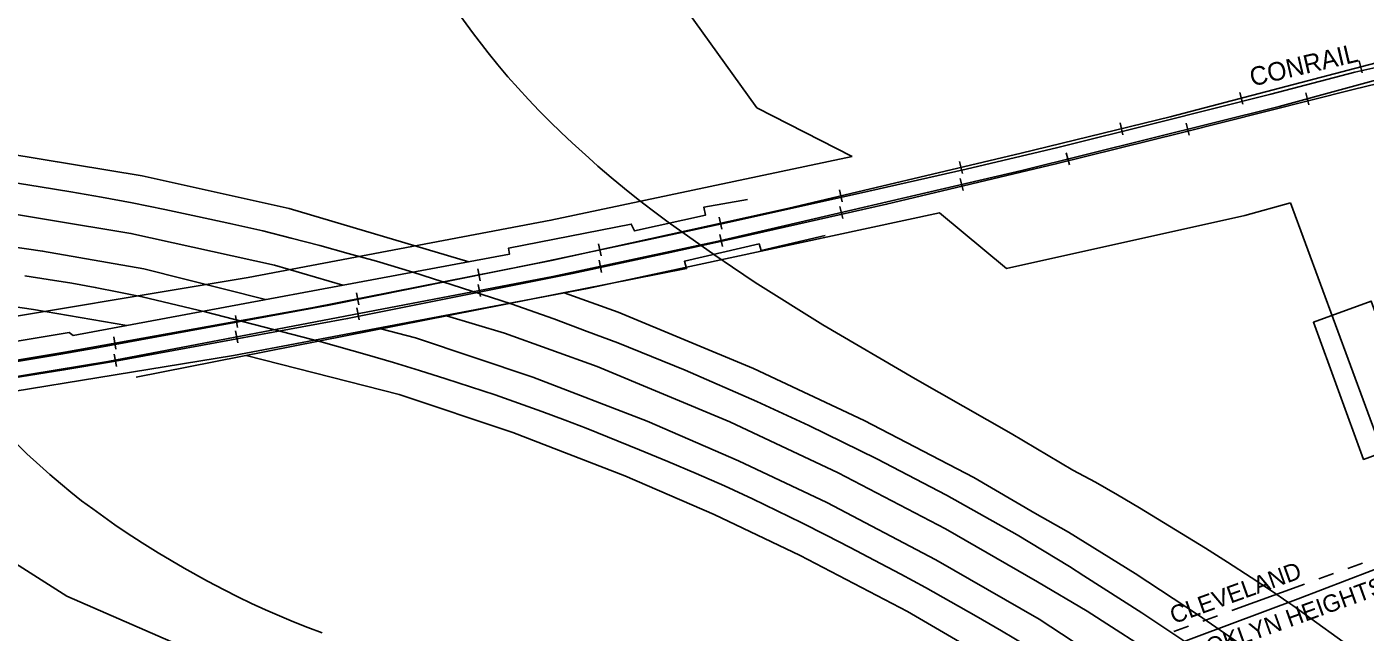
# Model space of a CAD drawing. Extents: x -25029 to 2274964, y -81170 to 687028.
# Drawn here: x -16160 to -15076, y -64135 to -63645 of the extents above; entities that cross this region are included whole.
import ezdxf

# ---------------------------------------------------------------- set-up
doc = ezdxf.new("R2010")
doc.units = 0
for name, color, linetype in [('81911BEA - RW_X_Fee_RW', 7, 'Continuous'), ('BLDG', 7, 'Continuous'), ('BRIDGE', 7, 'Continuous'), ('DIVISIONS', 7, 'Continuous'), ('DV_X_Corp_Line', 7, 'Continuous'), ('GE_X_CL_100', 7, 'Continuous'), ('GE_X_CL_2000', 7, 'Continuous'), ('INTERSTATE', 7, 'Continuous'), ('PV_X_EOP', 7, 'Continuous'), ('RD_X_RR_1', 7, 'Continuous'), ('ROAD-NAME', 7, 'Continuous'), ('RR', 7, 'Continuous'), ('WALL', 7, 'Continuous')]:
    doc.layers.add(name, color=color, linetype=linetype)

msp = doc.modelspace()

# ---------------------------------------------------------------- linework, layer by layer
at = {"layer": '81911BEA - RW_X_Fee_RW'}
for p, q in [((-15569, -63710.4), (-15491.7, -63749.7)), ((-15043.9, -64039.7), (-15136.9, -63787.3)), ((-15421.1, -63795.3), (-15366.8, -63840.5)), ((-16127.7, -64105.8), (-16043.6, -64142.6))]:
    msp.add_line(p, q, dxfattribs=at)
for points in [[(-15569, -63710.4), (-15570.4, -63708.5), (-15618.7, -63641.2), (-15786.7, -63407.4)], [(-16227.1, -63888.9), (-15981, -63847.8), (-15735.8, -63801.4), (-15491.7, -63749.7)], [(-15366.8, -63840.5), (-15173.7, -63797.6), (-15136.9, -63787.3)], [(-16280.7, -63957.8), (-15992.8, -63910.9), (-15706.2, -63856.7), (-15421.1, -63795.3)], [(-16267.9, -64016.5), (-16169.4, -64079.3), (-16127.7, -64105.8)]]:
    msp.add_lwpolyline(points, dxfattribs=at)
at = {"layer": 'BLDG'}
msp.add_lwpolyline([(-15030.9, -63978), (-15071.5, -63866.9), (-15118.3, -63884), (-15077.7, -63995.1)], close=True, dxfattribs=at)
at = {"layer": 'BRIDGE'}
for points in [[(-16122.6, -63894.8), (-15769.3, -63828.8), (-15770.2, -63824.1), (-15670.7, -63804.5), (-15668.2, -63810), (-15610.7, -63797.3), (-15612, -63790.8), (-15576.5, -63784.5)], [(-15513.8, -63813.8), (-15565.6, -63826), (-15567.2, -63820.6), (-15627.7, -63834.6), (-15625.9, -63840.5), (-16071.7, -63928.6)]]:
    msp.add_lwpolyline(points, dxfattribs=at)
at = {"layer": 'DIVISIONS'}
for p, q in [((-15090.3, -64083.3), (-15078.5, -64079)), ((-15113.8, -64091.8), (-15102, -64087.6)), ((-15184.3, -64117.4), (-15125.5, -64096.1)), ((-15207.8, -64126), (-15196, -64121.7)), ((-15231.3, -64134.5), (-15219.5, -64130.2))]:
    msp.add_line(p, q, dxfattribs=at)
at = {"layer": 'DV_X_Corp_Line'}
for p, q in [((-15130.6, -64108.1), (-14835.3, -63994.1)), ((-15130.6, -64108.1), (-14835.3, -63994.1)), ((-14835.3, -63994.1), (-15130.6, -64108.1)), ((-14835.3, -63994.1), (-15130.6, -64108.1)), ((-16057.5, -64452.9), (-15130.6, -64108.1)), ((-16057.5, -64452.9), (-15130.6, -64108.1)), ((-15130.6, -64108.1), (-16057.5, -64452.9)), ((-15130.6, -64108.1), (-16057.5, -64452.9))]:
    msp.add_line(p, q, dxfattribs=at)
at = {"layer": 'GE_X_CL_2000'}
for points in [[(-15139, -64110.6), (-15152.3, -64101.5), (-15168.8, -64090.6), (-15187.8, -64078.3), (-15205.7, -64067.1), (-15259.1, -64034.3), (-15276.9, -64023.8), (-15294.8, -64013.5), (-15313, -64003.7), (-15363.1, -63974.2), (-15440.7, -63929.8), (-15515.7, -63886.2), (-15570.4, -63851.9), (-15588.7, -63839.5), (-15603.1, -63829.7), (-15640.7, -63803), (-15653.9, -63793.3), (-15665.1, -63784.7), (-15676.1, -63775.8), (-15687, -63766.8), (-15697.7, -63757.6), (-15705.2, -63750.9), (-15718.6, -63738.7), (-15727.6, -63730.2), (-15736.6, -63721.5), (-15745.4, -63712.7), (-15754, -63703.7), (-15762.4, -63694.5), (-15770.7, -63685.1), (-15778.7, -63675.6), (-15786.7, -63665.9), (-15799.4, -63649.2), (-15811.8, -63632.4)], [(-15223.2, -64141.9), (-15257.3, -64119.3), (-15304.1, -64089.4), (-15315.9, -64081.8), (-15358.3, -64056.2), (-15415.5, -64024.1), (-15471.9, -63994.6), (-15527, -63967.5), (-15568.9, -63948.2), (-15627, -63922.8), (-15681.7, -63900.8), (-15706.4, -63891.4), (-15733.5, -63881.1), (-15768, -63869), (-15847.7, -63843.3), (-15877.1, -63834.6), (-15900, -63828.2), (-15922.9, -63821.9), (-15946, -63815.9), (-15969.2, -63810), (-15995.7, -63804), (-16022, -63798.3), (-16048.4, -63792.7), (-16074.8, -63787.4), (-16099.7, -63782.8), (-16124.6, -63778.4), (-16149.4, -63774.2), (-16174.5, -63770.2)], [(-16161.9, -63846.5), (-16142.8, -63849.3), (-16123.8, -63852.4), (-16104.8, -63855.8), (-16085.8, -63859.5), (-16066.7, -63863.4), (-16015.9, -63875.6), (-15921.8, -63899.9), (-15884.6, -63910.3), (-15863.3, -63916.5), (-15842.1, -63923), (-15820.9, -63929.7), (-15781, -63942.9), (-15762.1, -63949.5), (-15743.1, -63956.3), (-15724.3, -63963.3), (-15707.1, -63969.9), (-15664, -63987.2), (-15641, -63996.7), (-15618.1, -64006.6), (-15595.3, -64016.6), (-15572.5, -64027), (-15552.5, -64036.7), (-15532.7, -64046.4), (-15513, -64056.4), (-15493.4, -64066.5), (-15474, -64076.8), (-15452.4, -64088.1), (-15432.5, -64098.9), (-15411.8, -64110.3), (-15391.3, -64122), (-15370.9, -64133.9), (-15350.9, -64145.9)], [(-16185.9, -63965.4), (-16160.2, -63990.5), (-16149.8, -63999.9), (-16141.5, -64007.3), (-16133, -64014.5), (-16124.5, -64021.5), (-16115.8, -64028.5), (-16106.8, -64035.2), (-16097.9, -64041.7), (-16088.9, -64048.2), (-16079.7, -64054.4), (-16066.7, -64062.7), (-16053.8, -64070.8), (-16032.7, -64083.1), (-16014, -64093.6), (-16000.5, -64100.8), (-15989.4, -64106.3), (-15978.3, -64111.7), (-15967, -64116.9), (-15955.7, -64121.9), (-15944.3, -64126.6), (-15932.7, -64131.2), (-15921.1, -64135.5)], [(-14895.8, -64307.4), (-14896, -64307.2), (-14906.3, -64298.1), (-14920.8, -64286), (-14926.1, -64281.6), (-14978.1, -64235), (-15032, -64190.2), (-15082.5, -64151.1), (-15115.4, -64127.4), (-15134.9, -64113.3), (-15139, -64110.6)]]:
    msp.add_lwpolyline(points, dxfattribs=at)
at = {"layer": 'INTERSTATE'}
for points in [[(-15802.3, -63835), (-15947.7, -63791.8), (-16066.9, -63765.5), (-16204.6, -63742.8), (-16303.6, -63731.4), (-16391.9, -63724.8), (-16502.7, -63721.5), (-16623, -63723.4), (-16742.8, -63728.9), (-16982.5, -63743.5), (-17202.2, -63757.5), (-17341.4, -63766.6), (-17561.1, -63780), (-17760.1, -63792.9), (-17851.6, -63798.8)], [(-15904.3, -63854), (-15959.5, -63837.7), (-16075.9, -63812), (-16211.2, -63789.6), (-16308.1, -63778.5), (-16394.4, -63772), (-16503, -63768.8), (-16621.5, -63770.7), (-16740.3, -63776.1), (-16979.6, -63790.7), (-17199.1, -63804.7), (-17338.4, -63813.8), (-17558.1, -63827.2), (-17757.1, -63840.1), (-17850, -63846.1)], [(-15966.8, -63865.7), (-16065.5, -63840.6), (-16147.4, -63826.4), (-16240.3, -63812.9), (-16335.3, -63803), (-16428.7, -63796.6), (-16530.1, -63795.2), (-16629.4, -63797.2), (-16766.5, -63803.7), (-16944.2, -63814.6), (-17123.4, -63826.1), (-17321.9, -63838.6), (-17502.9, -63850), (-17741.4, -63865.3), (-17849.1, -63872)], [(-16079.2, -63886.7), (-16154.9, -63873.6), (-16246.2, -63860.3), (-16339.4, -63850.6), (-16430.7, -63844.3), (-16529.9, -63843), (-16627.8, -63844.9), (-16763.9, -63851.4), (-16941.2, -63862.2), (-17120.4, -63873.7), (-17318.9, -63886.3), (-17499.9, -63897.7), (-17738.4, -63912.9), (-17847.5, -63919.8)], [(-15343.8, -64038.5), (-15393.4, -64009.8), (-15482.2, -63963.6), (-15571.8, -63921.4), (-15681.3, -63875.8), (-15725, -63860.1)], [(-15341.7, -64094.1), (-15416.1, -64051.3), (-15503.2, -64006), (-15591, -63964.6), (-15698.4, -63919.9), (-15773.4, -63892.9), (-15820.4, -63878.9)], [(-15340.3, -64124.6), (-15424, -64076.4), (-15512.4, -64030.1), (-15583.8, -63996.1), (-15657.7, -63964.1), (-15750.3, -63928.4), (-15845.4, -63896.6), (-15873.6, -63889.4)], [(-15338.3, -64181.6), (-15447.1, -64118.3), (-15533.8, -64072.8), (-15603.6, -64039.6), (-15675.8, -64008.3), (-15766.5, -63973.4), (-15858.8, -63942.5), (-15982.6, -63911)]]:
    msp.add_lwpolyline(points, dxfattribs=at)
at = {"layer": 'PV_X_EOP'}
for points in [[(-15343.8, -64038.5), (-15316.7, -64054.1), (-15262.6, -64087.6), (-15211.4, -64121.1), (-15162.3, -64155.2), (-14991.3, -64288.5), (-14971.2, -64307.2)], [(-15033.6, -64314), (-15042.8, -64305.8), (-15108.7, -64253.4), (-15179.7, -64200.2), (-15238.5, -64158.5), (-15301.4, -64117.9), (-15341.7, -64094.1)], [(-15340.5, -64124.5), (-15340.3, -64124.6), (-15294.8, -64154.4), (-15228.1, -64198.1), (-15195.8, -64221.3), (-15137.4, -64264.7), (-15073.5, -64318.6)]]:
    msp.add_lwpolyline(points, dxfattribs=at)
at = {"layer": 'RD_X_RR_1'}
for p, q in [((-15656.2, -63817), (-15597.3, -63804.3)), ((-15746.7, -63836.1), (-15656.2, -63817)), ((-15641.5, -63828.1), (-15582.6, -63815.2)), ((-15718.3, -63844.4), (-15641.5, -63828.1))]:
    msp.add_line(p, q, dxfattribs=at)
for points in [[(-15597.3, -63804.3), (-15486.7, -63779.8), (-15399.6, -63760.1), (-15325.2, -63742.4), (-15245.2, -63722.4), (-15152.7, -63699.3), (-15084.8, -63681.4), (-15055.6, -63675), (-14975.6, -63652.5), (-14863.3, -63619.7), (-14785.9, -63596.2), (-14696.2, -63569.1)], [(-15582.6, -63815.2), (-15463.9, -63788.4), (-15326.8, -63755.8), (-15225.4, -63730.7), (-15086.2, -63695.6), (-15025.1, -63680.7), (-14896.9, -63645), (-14754.6, -63601.6), (-14680.6, -63577.8)], [(-16104.8, -63905), (-15915.4, -63870.2), (-15746.7, -63836.1)], [(-16088.4, -63915.5), (-15900.5, -63881), (-15718.3, -63844.4)], [(-16209.1, -63922.4), (-16138.9, -63910.8), (-16104.8, -63905)], [(-16199.7, -63933.6), (-16130.2, -63922.6), (-16088.4, -63915.5)]]:
    msp.add_lwpolyline(points, dxfattribs=at)
at = {"layer": 'RR'}
for p, q in [((-15081.3, -63672.4), (-15078.8, -63682.1)), ((-15178, -63697.8), (-15175.5, -63707.4)), ((-15124.5, -63698.1), (-15121.9, -63707.8)), ((-15274.9, -63722.4), (-15272.5, -63732.1)), ((-15221.3, -63722.8), (-15218.9, -63732.5)), ((-15404.8, -63753.7), (-15402.5, -63763.5)), ((-15318.4, -63746.9), (-15315.9, -63756.6)), ((-15502.1, -63776.8), (-15499.8, -63786.5)), ((-15404.3, -63767.5), (-15402, -63777.3)), ((-15599.6, -63798.9), (-15597.4, -63808.7)), ((-15501.7, -63790.2), (-15499.4, -63800)), ((-15697.2, -63820.5), (-15695.1, -63830.2)), ((-15599.1, -63812.9), (-15596.8, -63822.6)), ((-15795, -63840.7), (-15793.1, -63850.5)), ((-15696.8, -63833.8), (-15694.7, -63843.6)), ((-15794.7, -63853.4), (-15792.9, -63863.2)), ((-15893.1, -63860.1), (-15891.2, -63869.9)), ((-15893, -63872.2), (-15891.1, -63882)), ((-15991.3, -63878.4), (-15989.6, -63888.2)), ((-16089.8, -63895.9), (-16088, -63905.8)), ((-15991.2, -63891), (-15989.3, -63900.8)), ((-16089.4, -63909.8), (-16087.5, -63919.7))]:
    msp.add_line(p, q, dxfattribs=at)
for points in [[(-14748.4, -63582.8), (-15006.8, -63658), (-15234.4, -63717.7), (-15355, -63747.1)], [(-14748.4, -63596.6), (-14933.7, -63651.1), (-15146, -63709.2), (-15354.5, -63761.1)], [(-15355, -63747.1), (-15544.1, -63791.8), (-15735.2, -63833.9), (-15929.3, -63872.4), (-16129.4, -63908.1), (-16229.9, -63924.9), (-16305.2, -63936.7), (-16398.3, -63950.8), (-16524.5, -63968.3), (-16580.8, -63975.6), (-16720.2, -63992.7), (-16860.3, -64008.3), (-16977.2, -64019.9), (-17090.4, -64030), (-17259.1, -64042.9), (-17411.4, -64052.5), (-17554.2, -64059.5), (-17744.8, -64065.7), (-17842.4, -64068.1)], [(-15354.5, -63761.1), (-15600.3, -63818.3), (-15734.2, -63846.9), (-16094.5, -63915.9), (-16242.5, -63940.1), (-16331.4, -63953.3), (-16461.5, -63972.2), (-16580.2, -63988.6), (-16735.2, -64007.6), (-16927.9, -64028.3), (-17078.7, -64042.1), (-17179, -64050.3), (-17369.8, -64063.3), (-17550.7, -64072.4), (-17758.9, -64079.6), (-17841.9, -64080.9)]]:
    msp.add_lwpolyline(points, dxfattribs=at)
at = {"layer": 'WALL'}
msp.add_lwpolyline([(-16122.6, -63894.8), (-16125.9, -63892.2), (-16258.8, -63914.5)], dxfattribs=at)

# ---------------------------------------------------------------- texts
at = {"layer": 'GE_X_CL_100'}
for s, p in [('CLEVELAND', (-15231.4, -64128.5)), ('BROOKLYN HEIGHTS', (-15240.3, -64168.1))]:
    msp.add_text(s, height=14, rotation=19.7964, dxfattribs=at).set_placement(p)
at = {"layer": 'ROAD-NAME'}
msp.add_text('CONRAIL', height=15, rotation=13.2319, dxfattribs=at).set_placement((-15167.9, -63693.1))

doc.saveas('drawing.dxf')
